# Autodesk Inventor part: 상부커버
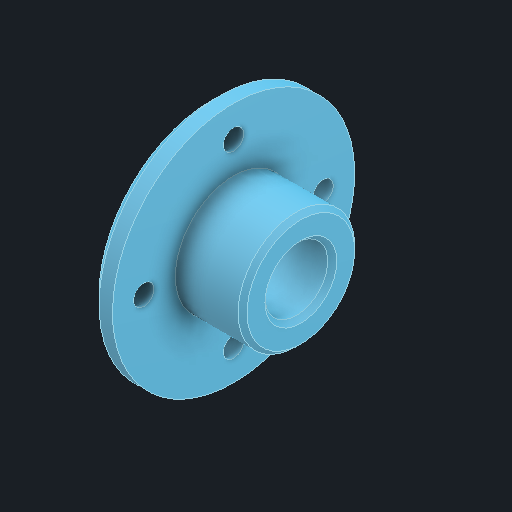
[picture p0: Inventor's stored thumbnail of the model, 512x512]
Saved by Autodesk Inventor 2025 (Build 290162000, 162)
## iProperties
Created: 2025-08
Part Number: 상부커버
Material: 알루미늄 6061
Document SubType Name: Modeling
Designer: infra14
Density: 2.71 g/cm^3
Appearance: 기본값
Author: jhkim
Sending System: Autodesk Inventor 2026
Preprocessor: ST-DEVELOPER v20.1
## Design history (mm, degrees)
feature "솔리드1"
node "솔리드2"
